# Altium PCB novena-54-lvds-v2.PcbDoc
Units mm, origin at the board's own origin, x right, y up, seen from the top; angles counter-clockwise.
Board outline 43.5 x 27.5 mm, 2 copper layers (Top Layer, Bottom Layer), stack 0.171 mm thick; 2 components, 34 nets, 872 pads, 28 vias.
Unrouted connection lines stored in the file: 1.
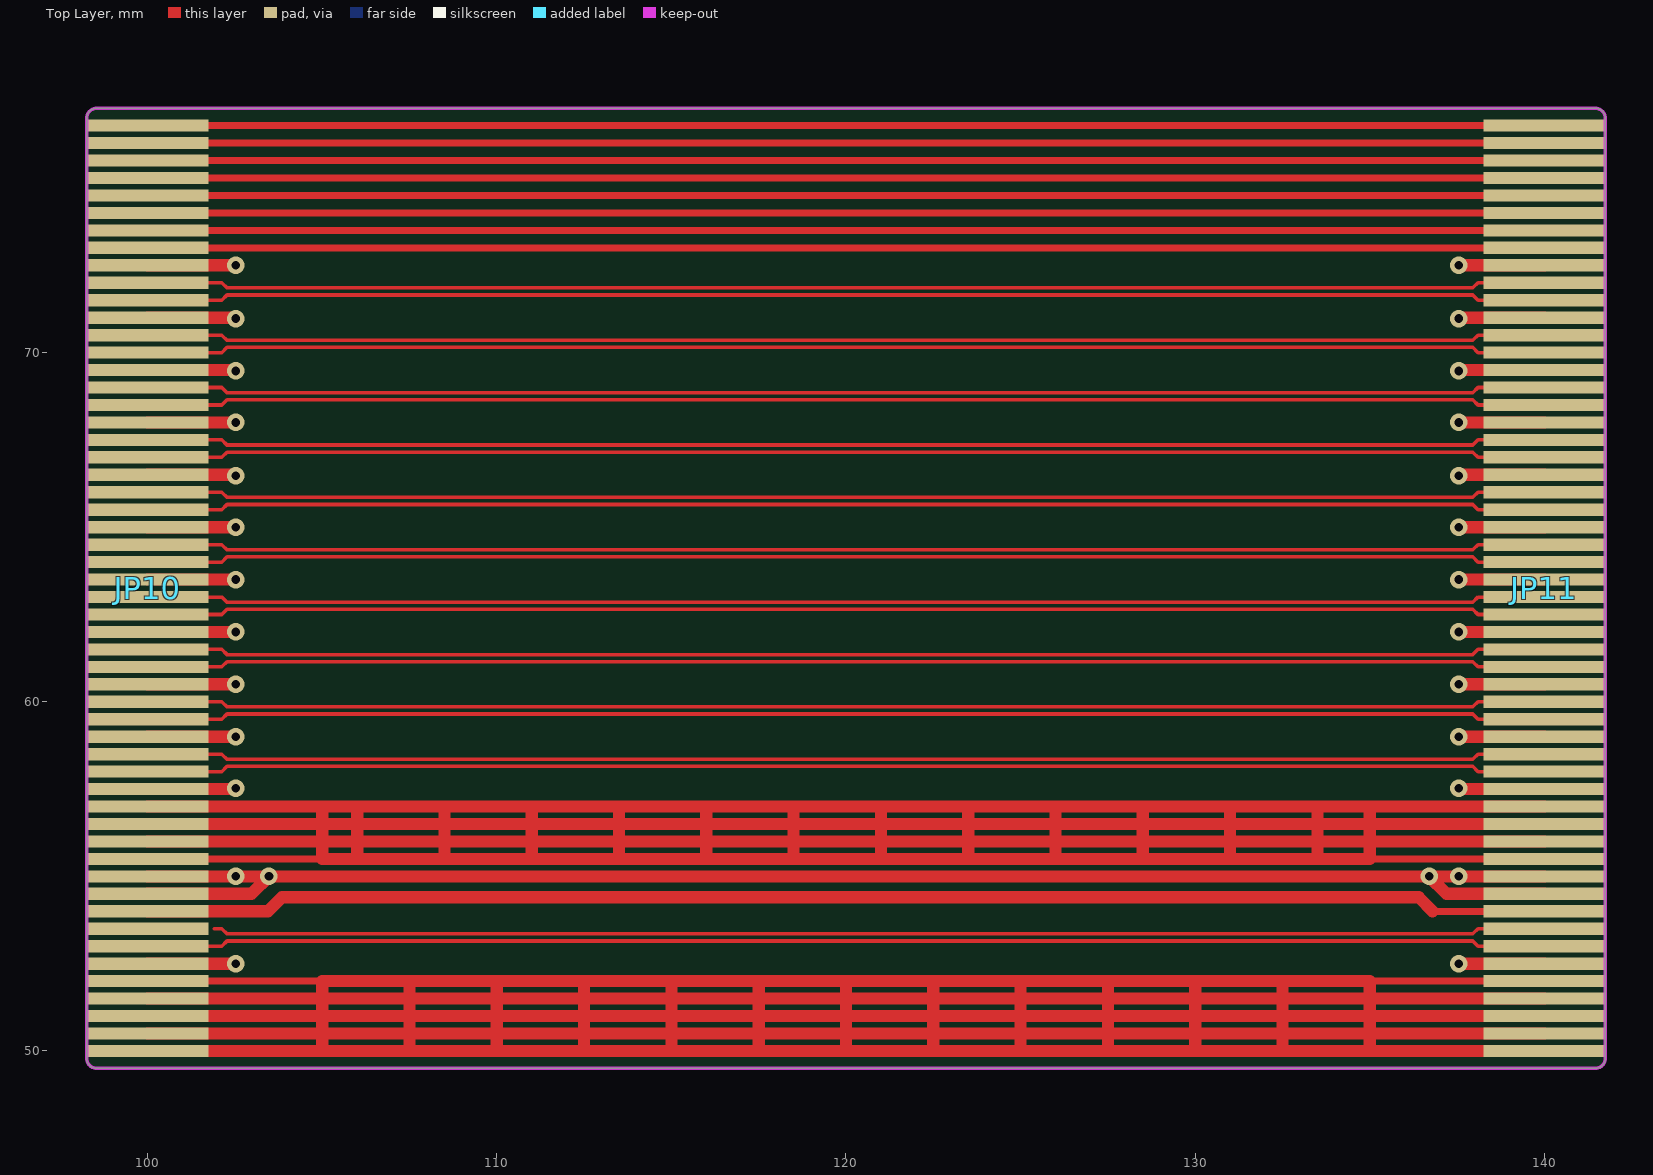
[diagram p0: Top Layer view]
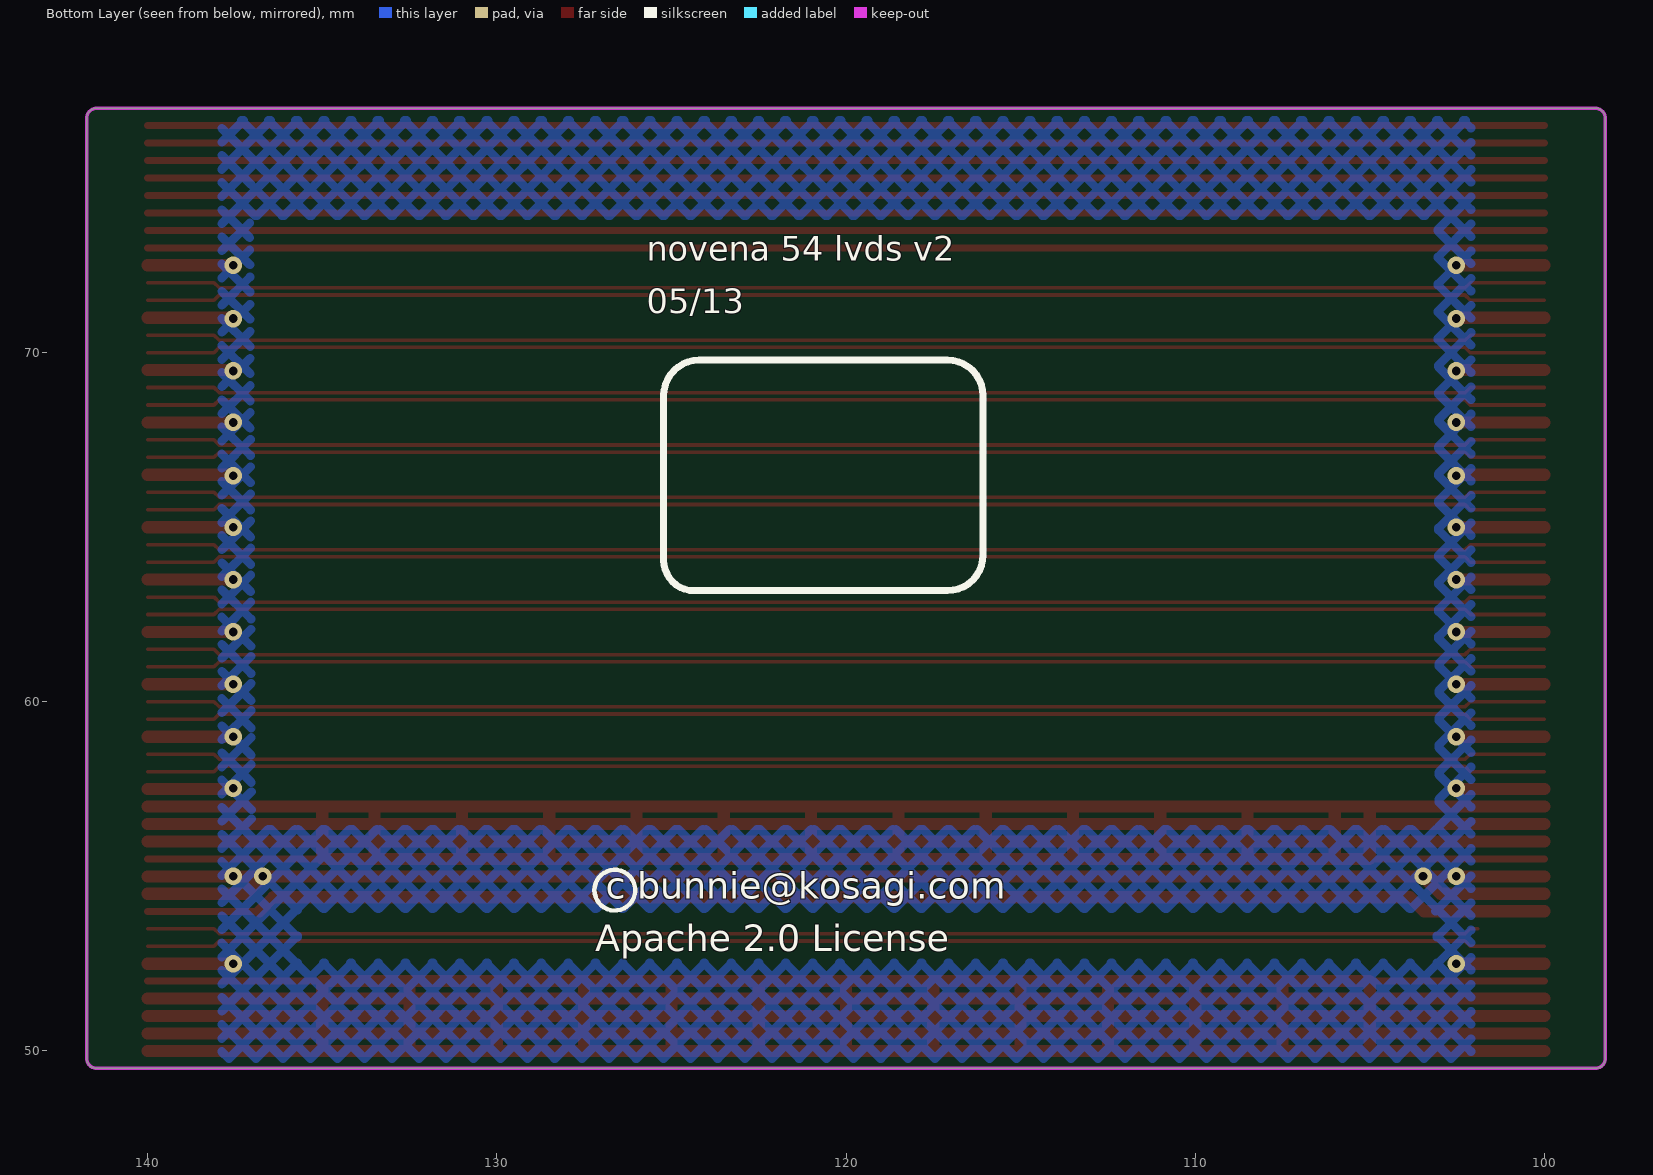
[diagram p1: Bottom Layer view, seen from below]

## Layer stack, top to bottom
Top Solder: solder mask 0.0102, Solder Resist, Dk 3.5
Top Layer: signal copper 0.0356
Dielectric1: core 0.1, Kapton, Dk 3.2
Bottom Layer: signal copper 0.0356
Bottom Solder: solder mask 0.0102, Solder Resist, Dk 3.5

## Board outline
98.25,49.8 98.25,76.7 cw(c98.55,76.7) 98.55,77 141.45,77 cw(c141.45,76.7) 141.75,76.7 141.75,49.8 cw(c141.45,49.8) 141.45,49.5 98.55,49.5 cw(c98.55,49.8)

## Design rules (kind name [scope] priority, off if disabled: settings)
Clearance [All] p1: gap=0.1
DiffPairsRouting [All] p1: maxlimit=0.3 minlimit=0.102 mostfreqgap=0.102 toplayer_minwidth=0.381 toplayer_maxwidth=0.381 toplayer_prefwidth=0.381 bottomlayer_minwidth=0.381 bottomlayer_maxwidth=0.381 bottomlayer_prefwidth=0.381 maxuncoupledlength=12.7
MinimumSolderMaskSliver [All] p1 off: minsoldermaskwidth=0.254
NetAntennae [All] p1 off: netantennaetolerance=0
PolygonConnect [All] p1: connectstyle=Direct reliefconductorwidth=0.254 reliefentries=4 polygonreliefangle="90 Angle" airgapwidth=0.254
RoomDefinition cable [InComponentClass('cable')] p1: confinementstyle=ConfineIn formatcopy=TRUE lockcomponents=FALSE outline 94.946,49.196 94.946,80.934 105.004,80.934 105.004,77.304 145.054,77.304 145.054,45.566 134.996,45.566 134.996,49.196
RoutingVias [All] p1: holewidth=0.25 width=0.5 viastyle="Through Hole" minholewidth=0.25 minwidth=0.5 maxholewidth=0.25 maxwidth=0.5
SilkToSilkClearance [All] p1 off: silktosilkclearance=0.254
SilkToSolderMaskClearance [IsPad] p1 off: minsilkscreentomaskgap=0.254 clearancetoexposedcopper=TRUE
SolderMaskExpansion [All] p1: expansion=0.102
Width [All] p1: maxlimit=10 minlimit=0.1 preferedwidth=0.2 minimp=50.000000 maximp=50.000000 favimp=50.000000
24 further rules are at their usual default settings.

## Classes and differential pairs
differential pair LVDS0_CLK: +LVDS0_CLK_P -LVDS0_CLK_N
differential pair LVDS0_TX_0: +LVDS0_TX_0_P -LVDS0_TX_0_N
differential pair LVDS0_TX_1: +LVDS0_TX_1_P -LVDS0_TX_1_N
differential pair LVDS0_TX_2: +LVDS0_TX_2_P -LVDS0_TX_2_N
differential pair LVDS0_TX_3: +LVDS0_TX_3_P -LVDS0_TX_3_N
differential pair LVDS1_CLK: +LVDS1_CLK_P -LVDS1_CLK_N
differential pair LVDS1_TX0: +LVDS1_TX0_P -LVDS1_TX0_N
differential pair LVDS1_TX1: +LVDS1_TX1_P -LVDS1_TX1_N
differential pair LVDS1_TX2: +LVDS1_TX2_P -LVDS1_TX2_N
differential pair LVDS1_TX_3: +LVDS1_TX_3_P -LVDS1_TX_3_N
differential pair USB_VID: +USB_VID_P -USB_VID_N

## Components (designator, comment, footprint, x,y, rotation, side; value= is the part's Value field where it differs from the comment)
JP10 "54-pin FFC MOLEX 51296-5494 or equiv" FPC-54-EDGE-0.3MM 100,50 r90 top
JP11 "54-pin FFC MOLEX 51296-5494 or equiv" FPC-54-EDGE-0.3MM 140,76.5 r270 top

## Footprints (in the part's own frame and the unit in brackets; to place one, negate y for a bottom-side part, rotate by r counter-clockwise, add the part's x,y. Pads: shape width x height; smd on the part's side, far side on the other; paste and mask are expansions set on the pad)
FPC-54-EDGE-0.3MM [mm] "FPC edge, 0.3mm height, 54 points"
  rect 0.35x3.5 smd: 1(0,0) 2(0.5,0) 3(1,0) 4(1.5,0) 5(2,0) 6(2.5,0) 7(3,0) 8(3.5,0) 9(4,0) 10(4.5,0) 11(5,0) 12(5.5,0) 13(6,0) 14(6.5,0) 15(7,0) 16(7.5,0) 17(8,0) 18(8.5,0) 19(9,0) 20(9.5,0) 21(10,0) 22(10.5,0) 23(11,0) 24(11.5,0) 25(12,0) 26(12.5,0) 27(13,0) 28(13.5,0) 29(14,0) 30(14.5,0) 31(15,0) 32(15.5,0) 33(16,0) 34(16.5,0) 35(17,0) 36(17.5,0) 37(18,0) 38(18.5,0) 39(19,0) 40(19.5,0) 41(20,0) 42(20.5,0) 43(21,0) 44(21.5,0) 45(22,0) 46(22.5,0) 47(23,0) 48(23.5,0) 49(24,0) 50(24.5,0) 51(25,0) 52(25.5,0) 53(26,0) 54(26.5,0)
  Keep-Out Layer lines w0.1: -0.5,-4.7 -0.5,1.45 cw(c-0.2,1.45) -0.2,1.75 26.7,1.75 cw(c26.7,1.45) 27,1.45 27,-4.7
  body extent -0.5,-3.7 27,1.75, height 0.2

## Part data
JP10 JP11: library part HEADER_54, "Flat flex connector, 54 positions"

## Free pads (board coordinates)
  rect 0.508x0.051 on Bottom Overlay: 1(116.94,64.021) 1(118.057,66.815) 1(118.642,56.051) 1(119.124,67.272) 1(119.835,63.869) 1(119.988,63.818) 1(120.038,67.933) 1(120.14,63.767) 1(121.613,68.542) 1(121.969,68.644) 1(122.858,56.051) 1(122.858,61.284) 1(123.544,66.053) 1(123.544,66.104) 1(123.645,68.441)
  rect 0.406x0.051 on Bottom Overlay: 1(116.94,64.072) 1(117.498,64.58) 1(117.498,64.631) 1(117.549,64.681) 1(117.6,64.732) 1(117.6,67.933) 1(117.6,68.593) 1(117.651,64.783) 1(118.108,66.967) 1(118.21,64.021) 1(118.26,64.072) 1(119.124,67.323) 1(119.226,64.224) 1(119.226,67.12) 1(119.276,64.173) 1(119.276,67.069) 1(119.327,64.123) 1(119.327,67.018) 1(119.429,64.072) 1(120.038,67.882) 1(121.258,64.986) 1(121.258,65.037) 1(121.258,65.088) 1(121.512,65.545) 1(121.512,68.339) 1(121.562,65.647) 1(121.562,68.288) 1(121.562,68.491) 1(121.613,65.697) 1(121.664,65.748) 1(121.715,65.799) 1(121.816,68.949) 1(122.731,67.221) 1(122.858,56.001) 1(122.934,63.818) 1(123.391,64.123) 1(123.442,69.05) 1(123.594,66.002) 1(123.645,65.951) 1(123.696,65.85) 1(124.102,68.898)
  rect 0.305x0.051 on Bottom Overlay: 1(116.94,68.898) 1(117.397,65.139) 1(117.397,65.189) 1(117.397,65.24) 1(117.397,65.393) 1(117.397,65.443) 1(117.397,65.494) 1(117.397,65.545) 1(117.397,65.596) 1(117.397,65.647) 1(117.397,65.697) 1(117.397,65.748) 1(117.397,65.799) 1(117.397,65.85) 1(117.397,65.901) 1(117.397,65.951) 1(117.397,66.002) 1(117.397,66.053) 1(117.397,66.256) 1(117.448,64.427) 1(117.448,64.478) 1(117.549,67.831) 1(117.549,68.695) 1(117.549,68.745) 1(118.108,67.018) 1(118.26,66.612) 1(118.311,64.173) 1(118.311,64.224) 1(118.311,64.275) 1(118.311,64.326) 1(118.311,64.377) 1(118.311,64.427) 1(118.311,64.478) 1(118.311,64.529) 1(118.311,64.58) 1(118.311,64.631) 1(118.311,64.681) 1(118.311,64.732) 1(118.311,64.783) 1(118.311,64.834) 1(118.311,64.885) 1(118.311,64.935) 1(118.311,64.986) 1(118.311,65.037) 1(118.311,65.088) 1(118.311,65.139) 1(118.311,65.189) 1(118.311,65.24) 1(118.311,66.561) 1(118.616,65.85) 1(118.616,65.901) 1(118.616,65.951) 1(118.616,66.002) 1(118.616,66.053) 1(118.667,65.393) 1(118.667,65.443) 1(118.718,65.037) 1(118.718,65.088) 1(118.718,65.139) 1(118.718,65.189) 1(118.768,64.885) 1(118.768,64.935) 1(118.768,64.986) 1(118.819,64.783) 1(118.819,64.834) 1(118.87,64.681) 1(118.921,64.58) 1(119.022,69.355) 1(119.581,68.187) 1(119.632,68.136) 1(119.683,65.088) 1(119.683,65.139) 1(119.683,65.189) 1(119.683,65.24) 1(119.683,65.393) 1(119.683,65.443) 1(119.683,65.494) 1(119.683,65.545) 1(119.683,65.596) 1(119.683,65.647) 1(119.683,65.697) 1(119.683,65.748) 1(119.683,65.799) 1(119.683,65.85) 1(119.683,65.901) 1(119.683,65.951) 1(119.683,66.002) 1(119.683,66.053) 1(119.734,68.085) 1(119.784,66.358) 1(119.784,68.034) 1(120.089,66.053) 1(120.191,68.644) 1(120.292,65.901) 1(120.343,65.85) 1(121.258,64.885) 1(121.512,68.39) 1(121.512,68.441) 1(121.867,65.951) 1(121.918,66.002) 1(121.969,66.053) 1(122.782,64.173) 1(122.782,64.224) 1(122.782,64.275) 1(122.782,64.326) 1(122.782,64.377) 1(122.782,64.427) 1(122.782,64.478) 1(122.782,64.529) 1(122.782,64.58) 1(122.782,64.631) 1(122.782,64.681) 1(122.782,64.732) 1(122.782,64.783) 1(122.782,64.834) 1(122.782,64.885) 1(122.782,64.935) 1(122.782,64.986) 1(122.782,65.037) 1(122.782,65.088) 1(122.782,65.139) 1(122.782,65.189) 1(122.782,65.24) 1(122.782,65.291) 1(122.782,65.342) 1(122.782,65.393) 1(122.782,65.443) 1(122.782,65.494) 1(122.782,65.545) 1(122.782,65.596) 1(122.782,65.647) 1(122.782,65.697) 1(122.782,65.748) 1(122.782,65.799) 1(122.782,65.85) 1(122.782,65.901) 1(122.782,65.951) 1(122.782,66.002) 1(122.782,66.053) 1(122.782,66.104) 1(122.782,66.155) 1(122.782,66.205) 1(122.782,66.256) 1(122.782,66.307) 1(122.782,66.358) 1(122.782,66.409) 1(122.782,66.459) 1(122.782,66.51) 1(122.782,66.561) 1(122.782,66.612) 1(122.782,66.663) 1(122.782,66.713) 1(122.782,66.764) 1(122.782,66.815) 1(122.782,66.866) 1(122.782,66.917) 1(122.782,66.967) 1(122.782,67.018) 1(122.782,67.069) 1(122.782,67.12) 1(123.34,68.949) 1(123.391,68.339) 1(123.747,65.748) 1(123.798,65.647) 1(123.848,65.596) 1(123.899,65.494) 1(123.95,65.393) 1(123.95,65.443) 1(124.001,65.342) 1(124.052,65.291) 1(124.153,65.139) 1(124.204,65.088)
  rect 0.356x0.051 on Bottom Overlay: 1(116.965,64.123) 1(117.473,64.529) 1(117.524,69.253) 1(117.575,67.882) 1(117.575,68.644) 1(117.727,64.834) 1(117.778,64.885) 1(118.184,66.713) 1(118.235,66.663) 1(118.286,64.123) 1(118.616,56.001) 1(118.616,61.335) 1(118.845,64.732) 1(118.895,64.631) 1(118.946,64.529) 1(118.997,64.478) 1(119.048,64.377) 1(119.048,64.427) 1(119.099,64.326) 1(119.149,64.275) 1(119.149,67.374) 1(119.353,66.967) 1(119.454,66.815) 1(119.505,66.713) 1(119.505,66.764) 1(119.556,66.663) 1(119.582,56.305) 1(119.607,66.561) 1(119.607,66.612) 1(119.657,66.51) 1(119.708,66.459) 1(119.759,66.409) 1(119.81,66.307) 1(120.064,69.101) 1(120.165,66.002) 1(120.216,65.951) 1(120.318,68.695) 1(121.232,64.935) 1(121.74,65.85) 1(121.791,65.901) 1(121.791,68.593) 1(121.918,56.305) 1(122.756,67.171) 1(122.756,67.323) 1(122.807,64.123) 1(122.884,61.335) 1(122.959,63.767) 1(123.569,66.205) 1(123.671,65.901) 1(123.671,68.491) 1(123.721,65.799) 1(123.772,65.697) 1(123.874,65.545)
  rect 0.254x0.051 on Bottom Overlay: 1(116.965,64.173) 1(116.965,64.224) 1(116.965,64.275) 1(117.422,64.377) 1(117.473,69.203) 1(117.575,69.304) 1(117.778,67.983) 1(117.829,64.935) 1(118.184,68.085) 1(118.235,68.034) 1(118.337,66.51) 1(118.387,66.459) 1(118.387,67.933) 1(118.438,66.358) 1(118.616,55.95) 1(118.616,61.385) 1(118.641,65.494) 1(118.641,65.545) 1(118.641,65.596) 1(118.641,65.647) 1(118.641,65.697) 1(118.641,65.748) 1(118.641,65.799) 1(118.692,65.24) 1(119.2,68.491) 1(119.2,69.152) 1(119.251,68.441) 1(119.251,69.203) 1(119.302,68.39) 1(119.353,68.339) 1(119.454,68.288) 1(119.505,68.237) 1(119.632,56.255) 1(119.708,65.037) 1(119.911,68.999) 1(119.962,69.05) 1(120.064,67.831) 1(120.115,68.542) 1(120.115,69.152) 1(120.165,68.593) 1(120.369,63.665) 1(120.369,68.745) 1(120.419,65.799) 1(120.47,65.748) 1(121.232,64.834) 1(121.232,68.949) 1(121.334,68.745) 1(121.791,69.152) 1(121.791,69.203) 1(121.842,69.253) 1(121.868,56.255) 1(121.893,68.034) 1(121.943,67.983) 1(121.994,66.104) 1(121.994,67.933) 1(122.045,66.155) 1(122.096,66.205) 1(122.096,67.882) 1(122.147,67.831) 1(122.248,67.78) 1(122.807,67.374) 1(122.884,55.95) 1(122.884,61.385) 1(122.959,63.716) 1(123.163,68.085) 1(123.163,68.136) 1(123.213,68.187) 1(123.264,68.237) 1(123.315,68.288) 1(123.417,68.898) 1(123.467,68.39) 1(123.467,68.796) 1(123.518,68.745) 1(123.569,66.256) 1(123.569,68.644) 1(123.62,68.593) 1(123.671,68.542) 1(123.823,68.39) 1(123.874,68.339) 1(123.925,68.288) 1(123.975,68.237) 1(124.026,68.187) 1(124.077,65.24) 1(124.128,65.189) 1(124.128,68.136) 1(124.179,68.085) 1(124.229,65.037) 1(124.28,64.986) 1(124.28,68.034) 1(124.331,64.935) 1(124.382,64.885) 1(124.382,67.983) 1(124.433,64.834) 1(124.433,67.933) 1(124.483,64.783) 1(124.534,64.732)
  rect 0.152x0.051 on Bottom Overlay: 1(116.965,64.377) 1(116.965,64.427) 1(116.965,64.478) 1(116.965,64.529) 1(116.965,64.58) 1(116.965,64.631) 1(116.965,64.681) 1(116.965,64.732) 1(116.965,64.783) 1(117.422,66.358) 1(117.473,65.088) 1(117.473,67.983) 1(117.473,68.034) 1(117.473,68.085) 1(117.473,68.136) 1(117.473,68.187) 1(117.473,68.237) 1(117.473,68.288) 1(117.473,68.339) 1(117.473,68.39) 1(117.473,68.441) 1(117.473,68.491) 1(117.473,68.542) 1(117.473,68.898) 1(117.473,68.949) 1(117.473,68.999) 1(117.473,69.05) 1(117.473,69.101) 1(117.473,69.152) 1(117.879,64.986) 1(118.616,55.899) 1(118.845,68.847) 1(118.895,68.796) 1(118.895,69.203) 1(118.946,68.745) 1(119.149,69.05) 1(119.2,67.475) 1(119.861,68.898) 1(120.064,67.78) 1(121.232,64.732) 1(121.232,69.101) 1(121.893,69.304) 1(121.994,68.796) 1(122.147,68.593) 1(122.197,66.307) 1(122.248,68.491) 1(122.299,68.441) 1(122.35,68.39) 1(122.401,68.339) 1(122.858,67.425) 1(122.884,55.899) 1(123.112,67.983) 1(124.128,68.847)
  rect 0.203x0.051 on Bottom Overlay: 1(116.99,64.326) 1(117.397,66.307) 1(117.448,64.326) 1(117.549,67.78) 1(117.702,68.542) 1(117.752,68.491) 1(117.803,68.441) 1(117.854,68.034) 1(117.854,68.39) 1(117.905,68.339) 1(117.956,68.288) 1(118.006,68.237) 1(118.057,68.187) 1(118.108,67.069) 1(118.108,68.136) 1(118.26,68.695) 1(118.311,67.983) 1(118.362,68.847) 1(118.413,66.409) 1(118.464,66.307) 1(118.464,67.882) 1(118.514,66.256) 1(118.921,69.253) 1(118.972,68.695) 1(118.972,69.304) 1(119.022,68.644) 1(119.073,68.593) 1(119.073,69.406) 1(119.124,68.542) 1(119.175,67.425) 1(119.175,69.101) 1(119.327,69.253) 1(119.886,68.949) 1(120.089,68.491) 1(121.258,64.783) 1(121.258,68.847) 1(121.258,68.898) 1(121.308,68.796) 1(121.359,68.695) 1(121.41,68.593) 1(121.41,68.644) 1(121.664,68.237) 1(121.715,68.187) 1(121.766,68.136) 1(121.816,68.085) 1(121.816,69.101) 1(121.867,69.05) 1(121.918,68.898) 1(121.969,68.847) 1(122.02,68.745) 1(122.07,68.695) 1(122.172,66.256) 1(122.172,68.542) 1(122.324,67.729) 1(122.985,63.665) 1(123.137,68.034) 1(123.442,68.847) 1(123.544,68.695) 1(123.594,66.307) 1(124.56,64.681)
  rect 1.27x0.051 on Bottom Overlay: 1(117.371,68.847) 1(120.75,61.233) 1(120.75,61.284) 1(120.75,61.335) 1(120.75,61.385)
  rect 0.102x0.051 on Bottom Overlay: 1(117.448,64.275) 1(117.549,67.729) 1(118.413,68.898) 1(118.591,61.436) 1(118.819,68.898) 1(119.124,68.999) 1(119.378,69.304) 1(119.658,56.204) 1(119.784,64.986) 1(120.242,68.034) 1(120.242,68.085) 1(120.496,65.697) 1(121.842,56.204) 1(122.426,68.288) 1(122.909,61.436) 1(123.391,69.101) 1(123.645,66.358) 1(124.306,69.05) 1(124.509,67.882)
  rect 1.626x0.051 on Bottom Overlay: 1(117.549,63.869)
  rect 1.727x0.051 on Bottom Overlay: 1(117.549,63.97) 1(118.718,66.917) 1(119.201,57.067) 1(119.251,57.169) 1(119.302,57.271) 1(119.302,57.321) 1(120.725,61.131) 1(122.198,57.22) 1(122.198,57.271) 1(122.198,57.321) 1(122.249,57.169) 1(122.299,57.067) 1(122.553,56.356)
  rect 1.372x0.051 on Bottom Overlay: 1(117.575,63.767)
  rect 1.473x0.051 on Bottom Overlay: 1(117.575,63.818) 1(120.75,61.182)
  rect 1.676x0.051 on Bottom Overlay: 1(117.575,63.919) 1(118.921,56.356) 1(119.277,57.22)
  rect 1.778x0.051 on Bottom Overlay: 1(117.575,68.796) 1(118.692,66.866) 1(118.921,56.407) 1(119.074,56.864) 1(119.124,56.915) 1(119.124,56.966) 1(119.175,57.017) 1(119.226,57.118) 1(122.274,57.118) 1(122.325,57.017) 1(122.376,56.915) 1(122.376,56.966) 1(122.579,56.407)
  rect 0.051x0.051 on Bottom Overlay: 1(117.879,68.085) 1(118.133,67.12) 1(118.489,67.831) 1(118.895,69.152) 1(122.197,66.358) 1(122.35,67.679)
  rect 0.61x0.051 on Bottom Overlay: 1(118.108,68.745) 1(118.642,56.102) 1(118.642,61.233) 1(119.988,67.983) 1(121.359,69.05) 1(122.858,61.233) 1(122.985,63.919)
  rect 0.457x0.051 on Bottom Overlay: 1(118.133,66.764) 1(118.616,61.284) 1(119.149,67.221) 1(119.2,67.171) 1(119.505,64.021) 1(119.607,63.97) 1(119.708,63.919) 1(119.81,66.256) 1(120.267,63.716) 1(121.283,65.139) 1(121.283,65.189) 1(121.334,65.24) 1(121.334,65.291) 1(121.385,65.342) 1(121.385,65.393) 1(121.435,65.443) 1(121.486,65.494) 1(121.537,65.596) 1(122.705,67.272) 1(123.518,66.155)
  rect 2.489x0.051 on Bottom Overlay: 1(118.464,58.591) 1(118.464,58.642) 1(118.464,58.693) 1(120.75,60.979)
  rect 2.54x0.051 on Bottom Overlay: 1(118.489,58.337) 1(118.489,58.388) 1(118.489,58.439) 1(118.489,58.49) 1(118.489,58.541) 1(118.489,58.744) 1(118.489,58.795) 1(118.489,58.845) 1(118.489,58.896) 1(118.489,58.947) 1(118.591,59.15) 1(122.909,59.15) 1(123.011,58.388) 1(123.011,58.439) 1(123.011,58.49) 1(123.011,58.541) 1(123.011,58.591) 1(123.011,58.642) 1(123.011,58.693) 1(123.011,58.744) 1(123.011,58.795) 1(123.011,58.845) 1(123.011,58.896) 1(123.011,58.947)
  rect 2.591x0.051 on Bottom Overlay: 1(118.515,58.236) 1(118.515,58.287) 1(118.515,58.998) 1(118.515,59.049) 1(118.515,59.099) 1(118.54,65.291) 1(118.54,65.342) 1(118.566,58.185) 1(122.934,58.185) 1(122.985,58.236) 1(122.985,58.287) 1(122.985,58.337) 1(122.985,58.998) 1(122.985,59.049)
  rect 2.946x0.051 on Bottom Overlay: 1(118.616,66.205)
  rect 2.997x0.051 on Bottom Overlay: 1(118.641,66.155) 1(118.692,66.104)
  rect 0.711x0.051 on Bottom Overlay: 1(118.642,61.182)
  rect 0.762x0.051 on Bottom Overlay: 1(118.667,56.153) 1(122.833,56.153) 1(122.833,61.182) 1(123.01,63.97) 1(123.925,68.949)
  rect 0.864x0.051 on Bottom Overlay: 1(118.667,56.204) 1(118.667,61.131) 1(120.75,62.198) 1(122.833,56.204) 1(122.833,61.131)
  rect 0.965x0.051 on Bottom Overlay: 1(118.667,61.081) 1(120.75,62.046) 1(120.75,62.097) 1(120.75,62.147) 1(122.833,61.081) 1(123.112,64.072)
  rect 1.016x0.051 on Bottom Overlay: 1(118.693,56.255) 1(120.725,61.995) 1(122.807,56.255)
  rect 1.118x0.051 on Bottom Overlay: 1(118.693,56.305) 1(118.693,61.03) 1(120.725,61.69) 1(122.807,56.305) 1(122.807,61.03) 1(123.798,68.999)
  rect 2.337x0.051 on Bottom Overlay: 1(118.693,58.134) 1(119.455,59.658) 1(122.807,58.134)
  rect 1.219x0.051 on Bottom Overlay: 1(118.693,60.979) 1(120.725,61.436) 1(122.807,60.979)
  rect 2.286x0.051 on Bottom Overlay: 1(118.718,59.201) 1(122.02,59.658) 1(122.731,59.201)
  rect 2.134x0.051 on Bottom Overlay: 1(118.845,58.083) 1(119.353,59.607) 1(122.147,59.607) 1(122.655,58.083)
  rect 1.829x0.051 on Bottom Overlay: 1(118.896,56.458) 1(118.997,56.712) 1(119.048,56.813) 1(119.048,57.982) 1(119.048,59.303) 1(119.099,57.931) 1(119.099,59.353) 1(119.302,57.372) 1(119.302,57.423) 1(122.198,57.372) 1(122.198,57.423) 1(122.35,59.404) 1(122.401,56.864) 1(122.401,57.931) 1(122.401,57.982) 1(122.401,59.353) 1(122.452,56.763) 1(122.452,56.813) 1(122.452,59.303) 1(122.503,56.712) 1(122.604,56.458)
  rect 1.93x0.051 on Bottom Overlay: 1(118.896,56.509) 1(119.201,57.829) 1(119.201,59.506) 1(119.302,57.525) 1(119.302,57.575) 1(122.198,57.525) 1(122.198,57.575) 1(122.299,57.829) 1(122.299,59.506) 1(122.35,57.88) 1(122.604,56.509)
  rect 2.032x0.051 on Bottom Overlay: 1(118.896,59.252) 1(119.251,57.728) 1(119.302,57.626) 1(119.302,57.677) 1(122.198,57.626) 1(122.198,57.677) 1(122.198,57.728) 1(122.604,59.252)
  rect 1.88x0.051 on Bottom Overlay: 1(118.921,56.559) 1(118.921,56.61) 1(118.972,56.661) 1(119.023,56.763) 1(119.023,58.033) 1(119.124,57.88) 1(119.124,59.404) 1(119.175,59.455) 1(119.277,57.474) 1(122.172,57.474) 1(122.325,59.455) 1(122.477,58.033) 1(122.528,56.61) 1(122.528,56.661) 1(122.579,56.559)
  rect 1.981x0.051 on Bottom Overlay: 1(119.226,57.779) 1(119.277,59.557) 1(120.75,61.081) 1(122.223,59.557) 1(122.274,57.779)
  rect 4.674x0.051 on Bottom Overlay: 1(120.725,60.115)
  rect 4.877x0.051 on Bottom Overlay: 1(120.725,60.268)
  rect 5.08x0.051 on Bottom Overlay: 1(120.725,60.42)
  rect 4.826x0.051 on Bottom Overlay: 1(120.75,59.709) 1(120.75,59.76) 1(120.75,60.217)
  rect 4.724x0.051 on Bottom Overlay: 1(120.75,59.811) 1(120.75,59.861) 1(120.75,60.166)
  rect 4.623x0.051 on Bottom Overlay: 1(120.75,59.912) 1(120.75,59.963) 1(120.75,60.014) 1(120.75,60.065)
  rect 4.928x0.051 on Bottom Overlay: 1(120.75,60.319)
  rect 5.029x0.051 on Bottom Overlay: 1(120.75,60.369)
  rect 5.131x0.051 on Bottom Overlay: 1(120.75,60.471)
  rect 5.232x0.051 on Bottom Overlay: 1(120.75,60.522)
  rect 5.334x0.051 on Bottom Overlay: 1(120.75,60.573) 1(120.75,60.623)
  rect 5.436x0.051 on Bottom Overlay: 1(120.75,60.674) 1(120.75,60.928)
  rect 5.537x0.051 on Bottom Overlay: 1(120.75,60.725) 1(120.75,60.776) 1(120.75,60.877)
  rect 5.639x0.051 on Bottom Overlay: 1(120.75,60.827)
  rect 2.184x0.051 on Bottom Overlay: 1(120.75,61.03)
  rect 1.168x0.051 on Bottom Overlay: 1(120.75,61.487) 1(120.75,61.538) 1(120.75,61.589) 1(120.75,61.639)
  rect 1.067x0.051 on Bottom Overlay: 1(120.75,61.741) 1(120.75,61.792) 1(120.75,61.843) 1(120.75,61.893) 1(120.75,61.944)
  rect 0.914x0.051 on Bottom Overlay: 1(121.512,68.999) 1(123.086,64.021)
  rect 0.66x0.051 on Bottom Overlay: 1(122.833,56.102)
  rect 0.559x0.051 on Bottom Overlay: 1(122.959,63.869)
  rect 2.642x0.051 on Bottom Overlay: 1(122.96,59.099)

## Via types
v1: diameter 0.5, hole 0.25, Top Layer to Bottom Layer, tented both sides, 28 vias

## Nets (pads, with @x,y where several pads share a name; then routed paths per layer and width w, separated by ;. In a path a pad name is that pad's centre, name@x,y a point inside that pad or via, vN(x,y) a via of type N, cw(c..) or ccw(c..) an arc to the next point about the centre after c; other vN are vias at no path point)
AUX_I2C_SCL: JP10.48 JP11.7 | length 40
  Top Layer w0.2: JP10.48 JP11.7
AUX_I2C_SDA: JP10.47 JP11.8 | length 40
  Top Layer w0.2: JP10.47 JP11.8
BATT_VDD: JP10.1 JP10.2 JP10.3 JP10.4 JP10.5 JP11.50 JP11.51 JP11.52 JP11.53 JP11.54 | length 226
  Top Layer w0.2: JP10.5 105,52 ; 135,52 JP11.50
  Top Layer w0.35: JP10.1 105,50 ; JP10.2 105,50.5 ; JP10.3 105,51 ; JP10.4 105,51.5 ; 120,52 120,51.5 ; JP11.54 135,50 ; JP11.53 135,50.5 ; JP11.52 135,51 ; JP11.51 135,51.5 ; 105,50 105,50.5 ; 105,50 107.5,50 ; 105,50.5 105,51 ; 105,50.5 107.5,50.5 ; 105,51 105,51.5 ; 105,51 107.5,51 ; 105,51.5 105,52 107.5,52 ; 105,51.5 107.5,51.5 ; 107.5,50 110,50 ; 107.5,50 107.5,50.5 ; 107.5,50.5 110,50.5 ; 107.5,50.5 107.5,51 ; 107.5,51 110,51 ; 107.5,51 107.5,51.5 ; 107.5,51.5 110,51.5 ; 107.5,51.5 107.5,52 ; 107.5,52 110,52 ; 110,50 112.5,50 ; 110,50 110,50.5 ; 110,50.5 112.5,50.5 ; 110,50.5 110,51 ; 110,51 112.5,51 ; 110,51 110,51.5 ; 110,51.5 112.5,51.5 ; 110,51.5 110,52 ; 110,52 112.5,52 ; 112.5,50 115,50 ; 112.5,50 112.5,50.5 ; 112.5,50.5 115,50.5 ; 112.5,50.5 112.5,51 ; 112.5,51 115,51 ; 112.5,51 112.5,51.5 ; 112.5,51.5 115,51.5 ; 112.5,51.5 112.5,52 ; 112.5,52 115,52 ; 115,50 117.5,50 ; 115,50 115,50.5 ; 115,50.5 117.5,50.5 ; 115,50.5 115,51 ; 115,51 117.5,51 ; 115,51 115,51.5 ; 115,51.5 117.5,51.5 ; 115,51.5 115,52 ; 115,52 117.5,52 ; 117.5,50 120,50 ; 117.5,50 117.5,50.5 ; 117.5,50.5 120,50.5 ; 117.5,50.5 117.5,51 ; 117.5,51 120,51 ; 117.5,51 117.5,51.5 ; 117.5,51.5 120,51.5 ; 117.5,51.5 117.5,52 ; 117.5,52 122.5,52 ; 120,50 120,50.5 ; 120,50 122.5,50 ; 120,50.5 120,51 ; 120,50.5 122.5,50.5 ; 120,51 120,51.5 ; 120,51 122.5,51 ; 120,51.5 122.5,51.5 ; 122.5,50 122.5,50.5 ; 122.5,50 125,50 ; 122.5,50.5 122.5,51 ; 122.5,50.5 125,50.5 ; 122.5,51 122.5,51.5 ; 122.5,51 125,51 ; 122.5,51.5 122.5,52 ; 122.5,51.5 125,51.5 ; 122.5,52 125,52 ; 125,50 127.5,50 ; 125,50 125,50.5 ; 125,50.5 127.5,50.5 ; 125,50.5 125,51 ; 125,51 127.5,51 ; 125,51 125,51.5 ; 125,51.5 127.5,51.5 ; 125,51.5 125,52 ; 125,52 127.5,52 ; 127.5,50 130,50 ; 127.5,50 127.5,50.5 ; 127.5,50.5 130,50.5 ; 127.5,50.5 127.5,51 ; 127.5,51 130,51 ; 127.5,51 127.5,51.5 ; 127.5,51.5 130,51.5 ; 127.5,51.5 127.5,52 ; 127.5,52 130,52 ; 130,50 132.5,50 ; 130,50 130,50.5 ; 130,50.5 132.5,50.5 ; 130,50.5 130,51 ; 130,51 132.5,51 ; 130,51 130,51.5 ; 130,51.5 132.5,51.5 ; 130,51.5 130,52 ; 130,52 132.5,52 ; 132.5,50 135,50 ; 132.5,50 132.5,50.5 ; 132.5,50.5 135,50.5 ; 132.5,50.5 132.5,51 ; 132.5,51 135,51 ; 132.5,51 132.5,51.5 ; 132.5,51.5 135,51.5 ; 132.5,51.5 132.5,52 ; 132.5,52 135,52 135,51.5 ; 135,50 135,50.5 ; 135,50.5 135,51 ; 135,51 135,51.5
GND: JP10.6 JP10.10 JP10.11 JP10.16 JP10.19 JP10.22 JP10.25 JP10.28 JP10.31 JP10.34 JP10.37 JP10.40 JP10.43 JP10.46 JP11.9 JP11.12 JP11.15 JP11.18 JP11.21 JP11.24 JP11.27 JP11.30 JP11.33 JP11.36 JP11.39 JP11.44 JP11.45 JP11.49 | length 106.1
  Top Layer w0.35: JP10.6 v1(102.525,52.5) ; JP10.10 102.975,54.5 v1(103.475,55) ; JP10.11 v1(102.525,55) v1(103.475,55) ; JP10.16 v1@102.45,57.5 ; JP10.19 v1@102.45,59 ; JP10.22 v1@102.45,60.5 ; JP10.25 v1@102.45,62 ; JP10.28 v1@102.45,63.5 ; JP10.31 v1@102.45,65 ; JP10.34 v1@102.45,66.5 ; JP10.37 v1@102.45,68 ; JP10.40 v1@102.45,69.5 ; JP10.43 v1@102.45,71 ; JP10.46 v1@102.45,72.5 ; v1(137.55,52.5) JP11.49 ; v1(137.55,57.525) 137.575,57.5 JP11.39 ; v1(137.55,59) JP11.36 ; v1(137.55,60.5) JP11.33 ; v1(137.55,62) JP11.30 ; v1(137.55,63.5) JP11.27 ; v1(137.55,65) JP11.24 ; v1@137.55,66.5 JP11.21 ; v1(137.55,68) JP11.18 ; v1@137.55,69.5 JP11.15 ; v1@137.55,71 JP11.12 ; v1(137.55,72.5) JP11.9 ; JP11.45 137.2,54.5 v1(136.7,55) ; JP11.44 v1(137.55,55) v1(136.7,55) ; v1(103.475,55) v1(136.7,55)
  other v1: 102.525,57.525 102.525,59 102.525,60.5 102.525,62 102.525,63.5 102.525,65 102.525,66.475 137.55,66.475 102.525,68 102.525,69.475 137.55,69.475 102.525,70.975 137.55,70.975 102.525,72.5
GPIO_PWM1: JP10.50 JP11.5 | length 40
  Top Layer w0.2: JP10.50 JP11.5
LCD_BL_ON: JP10.49 JP11.6 | length 40
  Top Layer w0.2: JP10.49 JP11.6
LCD_XM: JP10.52 JP11.3 | length 40
  Top Layer w0.2: JP10.52 JP11.3
LCD_XP: JP10.54 JP11.1 | length 40
  Top Layer w0.2: JP10.54 JP11.1
LCD_YM: JP10.51 JP11.4 | length 40
  Top Layer w0.2: JP10.51 JP11.4
LCD_YP: JP10.53 JP11.2 | length 40
  Top Layer w0.2: JP10.53 JP11.2
LVDS0_CLK_N: JP10.36 JP11.19 | length 40.1
  Top Layer w0.102: JP10.36 101.903,67.5 102.125,67.5 102.272,67.353 137.953,67.353 138.1,67.5 JP11.19
LVDS0_CLK_P: JP10.35 JP11.20 | length 40.1
  Top Layer w0.102: JP10.35 101.9,67 102.125,67 102.275,67.15 137.95,67.15 138.1,67 JP11.20
LVDS0_TX_0_N: JP10.45 JP11.10 | length 40.1
  Top Layer w0.102: JP10.45 101.903,72 102.125,72 102.272,71.853 137.953,71.853 138.1,72 JP11.10
LVDS0_TX_0_P: JP10.44 JP11.11 | length 40.1
  Top Layer w0.102: JP10.44 101.9,71.5 102.125,71.5 102.275,71.65 137.95,71.65 138.1,71.5 JP11.11
LVDS0_TX_1_N: JP10.42 JP11.13 | length 40.1
  Top Layer w0.102: JP10.42 101.903,70.5 102.125,70.5 102.272,70.353 137.953,70.353 138.1,70.5 JP11.13
LVDS0_TX_1_P: JP10.41 JP11.14 | length 40.1
  Top Layer w0.102: JP10.41 101.9,70 102.125,70 102.275,70.15 137.95,70.15 138.1,70 JP11.14
LVDS0_TX_2_N: JP10.39 JP11.16 | length 40.1
  Top Layer w0.102: JP10.39 101.903,69 102.125,69 102.272,68.853 137.953,68.853 138.1,69 JP11.16
LVDS0_TX_2_P: JP10.38 JP11.17 | length 40.1
  Top Layer w0.102: JP10.38 101.9,68.5 102.125,68.5 102.275,68.65 137.95,68.65 138.1,68.5 JP11.17
LVDS0_TX_3_N: JP10.33 JP11.22 | length 40.1
  Top Layer w0.102: JP10.33 101.903,66 102.125,66 102.272,65.853 137.953,65.853 138.1,66 JP11.22
LVDS0_TX_3_P: JP10.32 JP11.23 | length 40.1
  Top Layer w0.102: JP10.32 101.9,65.5 102.125,65.5 102.275,65.65 137.95,65.65 138.1,65.5 JP11.23
LVDS1_CLK_N: JP10.21 JP11.34 | length 40.1
  Top Layer w0.102: JP10.21 101.903,60 102.125,60 102.272,59.853 137.953,59.853 138.1,60 JP11.34
LVDS1_CLK_P: JP10.20 JP11.35 | length 40.1
  Top Layer w0.102: JP10.20 101.9,59.5 102.125,59.5 102.275,59.65 137.95,59.65 138.1,59.5 JP11.35
LVDS1_TX0_N: JP10.30 JP11.25 | length 40.1
  Top Layer w0.102: JP10.30 101.903,64.5 102.125,64.5 102.272,64.353 137.953,64.353 138.1,64.5 JP11.25
LVDS1_TX0_P: JP10.29 JP11.26 | length 40.1
  Top Layer w0.102: JP10.29 101.9,64 102.125,64 102.275,64.15 137.95,64.15 138.1,64 JP11.26
LVDS1_TX1_N: JP10.27 JP11.28 | length 40.1
  Top Layer w0.102: JP10.27 101.903,63 102.125,63 102.272,62.853 137.953,62.853 138.1,63 JP11.28
LVDS1_TX1_P: JP10.26 JP11.29 | length 40.1
  Top Layer w0.102: JP10.26 101.9,62.5 102.125,62.5 102.275,62.65 137.95,62.65 138.1,62.5 JP11.29
LVDS1_TX2_N: JP10.24 JP11.31 | length 40.1
  Top Layer w0.102: JP10.24 101.903,61.5 102.125,61.5 102.272,61.353 137.953,61.353 138.1,61.5 JP11.31
LVDS1_TX2_P: JP10.23 JP11.32 | length 40.1
  Top Layer w0.102: JP10.23 101.9,61 102.125,61 102.275,61.15 137.95,61.15 138.1,61 JP11.32
LVDS1_TX_3_N: JP10.18 JP11.37 | length 40.1
  Top Layer w0.102: JP10.18 101.903,58.5 102.125,58.5 102.272,58.353 137.953,58.353 138.1,58.5 JP11.37
LVDS1_TX_3_P: JP10.17 JP11.38 | length 40.1
  Top Layer w0.102: JP10.17 101.9,58 102.125,58 102.275,58.15 137.95,58.15 138.1,58 JP11.38
P3.3V: JP10.12 JP10.13 JP10.14 JP10.15 JP11.40 JP11.41 JP11.42 JP11.43 | length 181
  Top Layer w0.2: JP10.12 105,55.5 ; 135,55.5 JP11.43
  Top Layer w0.35: JP10.13 105,56 ; JP10.14 105,56.5 ; JP10.15 105,57 ; JP11.42 135,56 ; JP11.41 135,56.5 ; JP11.40 135,57 ; 105,56 105,55.5 106,55.5 ; 105,56 105,56.5 ; 105,56 106,56 ; 105,56.5 105,57 ; 105,56.5 106,56.5 ; 105,57 106,57 ; 106,55.5 108.5,55.5 ; 106,55.5 106,56 ; 106,56 108.5,56 ; 106,56 106,56.5 ; 106,56.5 108.5,56.5 ; 106,56.5 106,57 ; 106,57 108.5,57 ; 108.5,55.5 111,55.5 ; 108.5,55.5 108.5,56 ; 108.5,56 111,56 ; 108.5,56 108.5,56.5 ; 108.5,56.5 111,56.5 ; 108.5,56.5 108.5,57 ; 108.5,57 111,57 ; 111,55.5 113.5,55.5 ; 111,55.5 111,56 ; 111,56 113.5,56 ; 111,56 111,56.5 ; 111,56.5 113.5,56.5 ; 111,56.5 111,57 ; 111,57 113.5,57 ; 113.5,55.5 116,55.5 ; 113.5,55.5 113.5,56 ; 113.5,56 116,56 ; 113.5,56 113.5,56.5 ; 113.5,56.5 116,56.5 ; 113.5,56.5 113.5,57 ; 113.5,57 116,57 ; 116,55.5 118.5,55.5 ; 116,55.5 116,56 ; 116,56 118.5,56 ; 116,56 116,56.5 ; 116,56.5 118.5,56.5 ; 116,56.5 116,57 ; 116,57 118.5,57 ; 118.5,55.5 121,55.5 ; 118.5,55.5 118.5,56 ; 118.5,56 121,56 ; 118.5,56 118.5,56.5 ; 118.5,56.5 121,56.5 ; 118.5,56.5 118.5,57 ; 118.5,57 121,57 ; 121,55.5 123.5,55.5 ; 121,55.5 121,56 ; 121,56 123.5,56 ; 121,56 121,56.5 ; 121,56.5 123.5,56.5 ; 121,56.5 121,57 ; 121,57 123.5,57 ; 123.5,55.5 126,55.5 ; 123.5,55.5 123.5,56 ; 123.5,56 126,56 ; 123.5,56 123.5,56.5 ; 123.5,56.5 126,56.5 ; 123.5,56.5 123.5,57 ; 123.5,57 126,57 ; 126,55.5 128.5,55.5 ; 126,55.5 126,56 ; 126,56 128.5,56 ; 126,56 126,56.5 ; 126,56.5 128.5,56.5 ; 126,56.5 126,57 ; 126,57 128.5,57 ; 128.5,55.5 131,55.5 ; 128.5,55.5 128.5,56 ; 128.5,56 131,56 ; 128.5,56 128.5,56.5 ; 128.5,56.5 131,56.5 ; 128.5,56.5 128.5,57 ; 128.5,57 131,57 ; 131,55.5 133.5,55.5 ; 131,55.5 131,56 ; 131,56 133.5,56 ; 131,56 131,56.5 ; 131,56.5 133.5,56.5 ; 131,56.5 131,57 ; 131,57 133.5,57 ; 133.5,55.5 135,55.5 135,56 ; 133.5,55.5 133.5,56 ; 133.5,56 135,56 ; 133.5,56 133.5,56.5 ; 133.5,56.5 135,56.5 ; 133.5,56.5 133.5,57 ; 133.5,57 135,57 ; 135,56 135,56.5 ; 135,56.5 135,57
USB_VID_N: JP10.8 JP11.47 | length 38.2
  Top Layer w0.102: 101.903,53.5 102.125,53.5 102.272,53.353 137.953,53.353 138.1,53.5 JP11.47
USB_VID_P: JP10.7 JP11.48 | length 40.1
  Top Layer w0.102: JP10.7 102.125,53 102.275,53.15 137.95,53.15 138.1,53 JP11.48
USB_VID_P5V: JP10.9 JP11.46 | length 40.3
  Top Layer w0.2: 136.8,54 JP11.46
  Top Layer w0.35: JP10.9 103.45,54 103.85,54.4 136.4,54.4 136.8,54

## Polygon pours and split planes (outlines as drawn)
GND on Bottom Layer "bot - GND" (hatched 45Degree grid 0.55 track 0.25, remove dead copper, pour order 2): 102.1,49.775 102.1,76.625 102.125,76.65 137.825,76.65 137.875,76.6 137.875,49.775 137.85,49.75 102.025,49.75 102,49.725

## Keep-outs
Keep-Out Layer:
  lines w0.1: 98.25,49.8 ccw(c98.55,49.8) 98.55,49.5 104.7,49.5 135.3,49.5 141.45,49.5 ccw(c141.45,49.8) 141.75,49.8 141.75,76.7 ccw(c141.45,76.7) 141.45,77 135.5,77 104.7,77 98.55,77 ccw(c98.55,76.7) 98.25,76.7 98.25,49.8

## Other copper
Bottom Layer:
  pour cut-out: 103.075,54 103.075,52.517 135.698,52.517 135.706,52.525 135.706,54.044 135.675,54.075 103.2,54.075 103.125,54
  pour cut-out: 103.019,56.35 137.025,56.35 137.075,73.925 103.05,73.925

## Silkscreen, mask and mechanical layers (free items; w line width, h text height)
Bottom Overlay:
  circle w0.127: c126.621,54.606 r0.583
  lines w0.2: 116.076,64.199 ccw(c117.092,64.199) 117.092,63.183 124.353,63.183 ccw(c124.353,64.05) 125.22,64.05 125.22,68.771 ccw(c124.204,68.771) 124.204,69.787 117.092,69.787 ccw(c117.092,68.771) 116.076,68.771 116.076,64.199
  text "novena 54 lvds v2" at 125.712,72.631 h0.7
  text "05/13" at 125.712,71.131 h0.7
  text "c bunnie@kosagi.com" at 126.887,54.356 h0.76
  text "Apache 2.0 License" at 127.187,52.856 h0.76
Mechanical 1:
  lines w0.1: 101.925,49.5 101.925,77 138.125,77 138.125,49.5 101.925,49.5
  text "coverlay region" at 116.475,65.1 h0.5
Mechanical 3:
  lines w0.1: 101.275,77.375 107.475,83.575 129.425,83.575 ; 133.45,83 133.5,83 139.025,77.475 ; 209.95,69.25 209.95,78.15 218.05,78.15 ; 209.95,71.75 212.45,69.25 ; 209.95,73.7 214.25,69.4 ; 210,75.75 216.471,69.279 ; 210,77.75 218,69.75 ; 212,78.15 218,72.15 ; 214,78.15 218,74.15 ; 216,78.15 217.9,76.25 ; 219.5,59.75 224.5,59.75 ; 219.5,78 224.75,78
  lines w0.127: 175.027,59.749 216.937,59.749 ; 175.027,69.279 216.937,69.279 ; 177.567,61.019 178.837,59.749 180.107,61.019 ; 177.567,68.009 178.837,69.279 ; 178.837,59.875 178.837,69.279 ; 180.107,68.009 178.837,69.279 ; 184.69,70.62 185.96,71.89 ; 185.96,69.35 188.5,71.89 ; 187.23,69.35 188.5,70.62 ; 187.23,71.89 184.69,69.35 184.69,71.89 188.5,71.89 ; 188.5,69.35 188.5,71.89 ; 191.29,70.62 192.56,71.89 ; 192.56,69.35 195.1,71.89 ; 193.83,69.35 195.1,70.62 ; 193.83,71.89 191.29,69.35 191.29,71.89 195.1,71.89 ; 195.1,69.35 195.1,71.89 ; 203.029,70.602 204.299,71.872 ; 203.054,58.357 204.324,59.627 ; 203.054,59.627 203.054,57.087 ; 204.299,69.332 206.839,71.872 ; 204.324,57.087 206.864,59.627 206.864,57.087 203.054,57.087 ; 205.569,69.332 206.839,70.602 ; 205.569,71.872 203.029,69.332 203.029,71.872 206.839,71.872 ; 205.594,57.087 206.864,58.357 ; 205.594,59.627 203.054,57.087 ; 206.839,69.332 206.839,71.872 ; 219.98,61.02 221.25,59.75 ; 219.98,76.73 221.25,78 ; 222.52,61.02 221.25,59.75 ; 222.52,76.73 221.25,78 ; 221.25,59.75 221.25,78
  text "Board name: Novena 54 LVDS cable" at 163.597,97.219 h1
  text "Contact: bunnie@kosagi.com" at 163.597,94.679 h1
  text "immersion gold" at 130.05,83.275 h0.5
  text "Silk: white" at 197.263,82.847 h0.76
  text "Coverlay: clear" at 197.138,81.347 h0.76
  text "Contact Finish: Immersion gold" at 197.138,79.997 h0.76
  text "Material and thickness" at 148.357,75.629 h1.27
  text "stiffener (PI)" at 211.25,73.75 h0.7
  text "Coverlay 27.5 um" at 163.55,73.475 h0.76
  text "Stiffener area: 0.3mm +/-0.05mm TOTAL thickness" at 222.5,73 h0.7
  text "Top-bottom pair" at 178.837,70.549 h0.76 r45
  text "Copper 35 um" at 163.775,70.425 h0.76
  text "copper" at 203,70.25 h0.7
  text "PI: 25 um" at 161.5,64.25 h0.76
  text "Kapton (PI)" at 181.3,64.2 h0.76
  text "Copper 35 um" at 163.775,57.425 h0.76
  text "Coverlay 27.5 um" at 163.85,53.875 h0.76
  text "Mech via: 0.25mm hole / 0.5mm pad smallest" at 156.547,45.284 h0.76
  text "Route: 0.1mm / 0.1mm smallest" at 156.547,42.744 h0.76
